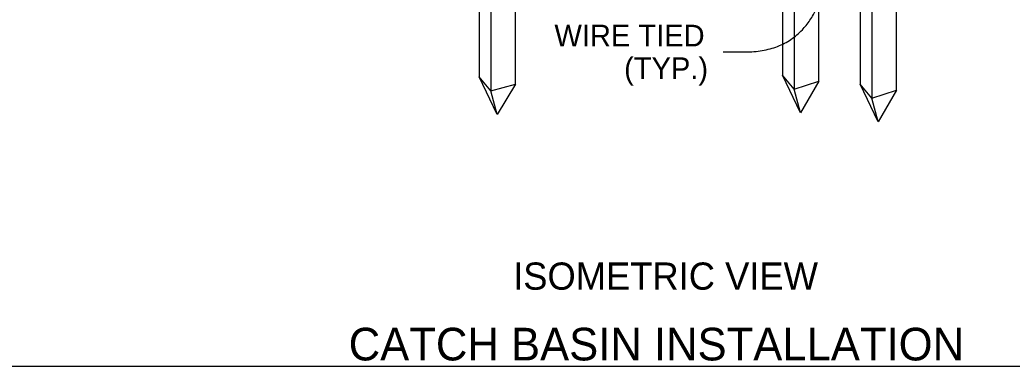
# Model space of a CAD drawing. Extents: x 99862 to 103680, y 99470 to 102076.
# Drawn here: x 101484 to 102215, y 100000 to 100254 of the extents above; entities that cross this region are included whole.
import ezdxf

# ---------------------------------------------------------------- set-up
doc = ezdxf.new("R2010")
doc.units = 0
for name, color, linetype in [('Level 1', 7, 'Continuous'), ('Level 15', 7, 'Continuous'), ('Level 2', 7, 'Continuous'), ('Level 20', 7, 'Continuous')]:
    doc.layers.add(name, color=color, linetype=linetype)

msp = doc.modelspace()

# ---------------------------------------------------------------- linework, layer by layer
at = {"layer": 'Level 1'}
msp.add_lwpolyline([(99862, 99999.5), (103151, 99999.5), (103151, 102075.5), (99862, 102075.5)], close=True, dxfattribs=at)
at = {"layer": 'Level 15'}
msp.add_line((102001.87, 100230.5), (102017.87, 100230.5), dxfattribs=at)
msp.add_open_spline([(102017.87, 100230.5), (102086.78, 100230.5), (102079.96, 100338.04)], degree=2, dxfattribs=at)
at = {"layer": 'Level 2'}
for p, q in [((101822.18, 100352.21), (101822.18, 100212.2)), ((101830.83, 100348.02), (101830.83, 100201.79)), ((102045.48, 100343.24), (102045.48, 100213.51)), ((101848.86, 100206.78), (101848.86, 100340.68)), ((102129.26, 100202.41), (102129.26, 100340.98)), ((102054.12, 100323.76), (102054.12, 100203.1)), ((102072.16, 100209.05), (102072.16, 100322.34)), ((102102.58, 100323.49), (102102.58, 100206.87)), ((102111.22, 100326.17), (102111.22, 100196.46)), ((101835.52, 100184.44), (101822.18, 100212.2)), ((101830.83, 100201.79), (101822.18, 100212.2)), ((102058.82, 100185.75), (102045.48, 100213.51)), ((102054.12, 100203.1), (102045.48, 100213.51)), ((101830.83, 100201.79), (101848.86, 100206.78)), ((101848.86, 100206.72), (101835.52, 100184.44)), ((102054.12, 100203.1), (102072.16, 100209.05)), ((102058.82, 100185.75), (102054.12, 100203.1)), ((102072.16, 100209.05), (102058.82, 100185.75)), ((102115.92, 100179.11), (102102.58, 100206.87)), ((102111.22, 100196.46), (102102.58, 100206.87)), ((101835.52, 100184.44), (101830.83, 100201.79)), ((102111.22, 100196.46), (102129.26, 100202.41)), ((102115.92, 100179.11), (102111.22, 100196.46)), ((102129.26, 100202.41), (102115.92, 100179.11))]:
    msp.add_line(p, q, dxfattribs=at)

# ---------------------------------------------------------------- texts
at = {"layer": 'Level 20'}
for s, height, p in [('WIRE TIED', 16, (101877.6, 100234.5)), ('(TYP.)', 16, (101928.9, 100210.5)), ('ISOMETRIC VIEW', 20, (101847.21, 100055.69)), ('CATCH BASIN INSTALLATION', 24, (101726.16, 100003.69))]:
    msp.add_text(s, height=height, dxfattribs=at).set_placement(p)

doc.saveas('drawing.dxf')
